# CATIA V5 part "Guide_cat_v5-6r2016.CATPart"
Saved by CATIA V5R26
Part number: Guide
Bounding box of the stored display mesh (mm): x -5 to 5, y -5 to 5, z -25 to 25
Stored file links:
  D:\_Deepak\CATIA\CATIA V5 2015 Parts Files\Tutorial Files\Tutorials\c16_catia_v5_6r2016_tut\Cam Follower mechanism\Guide_cat_v5-6r2016.CATPart
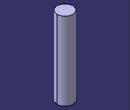
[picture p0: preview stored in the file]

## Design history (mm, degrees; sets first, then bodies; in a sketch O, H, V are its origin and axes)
Body1 (main body)
  Sketch1 on xy-plane, origin (0, 0, 0), H (1, 0, 0), V (0, 1, 0)
    circle A1 centre (0, 0) radius 5
    radius A1 = 5
  Pad1: profile Sketch1, direction (0, 0, 1), length 25, mirrored extent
